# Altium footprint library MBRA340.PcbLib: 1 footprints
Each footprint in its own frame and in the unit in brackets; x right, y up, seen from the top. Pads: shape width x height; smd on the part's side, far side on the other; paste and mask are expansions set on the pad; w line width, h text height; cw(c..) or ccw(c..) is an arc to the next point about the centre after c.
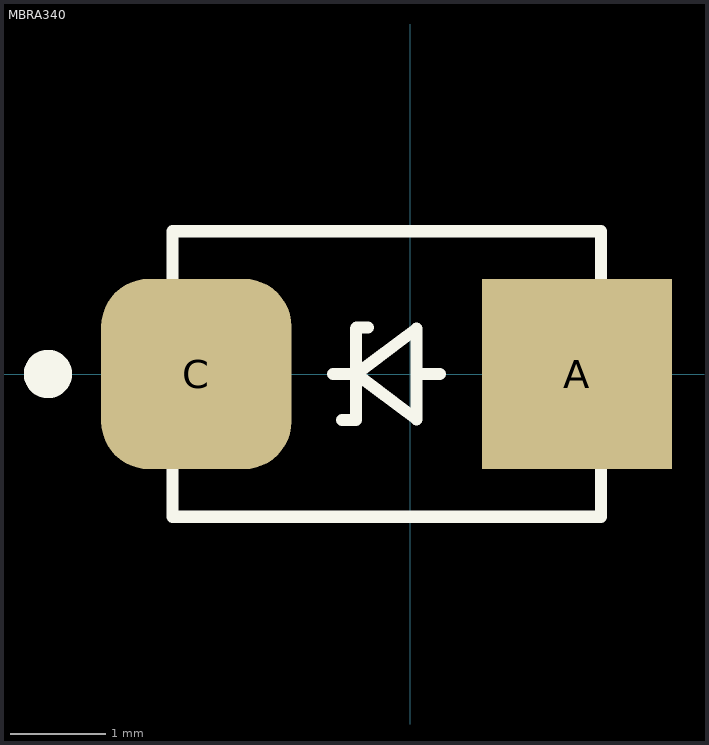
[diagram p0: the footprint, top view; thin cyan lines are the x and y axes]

## MBRA340 [mm]
pads (2):
  rect 2x2 smd: A(1.75,0)
  rrect50% 2x2 smd: C(-2.25,0)
Top Overlay:
  circle w0.254: c-3.81,0 r0.127
  lines w0.127: -0.815,0 -0.572,0 ; -0.721,-0.482 -0.574,-0.482 ; -0.572,-0.478 -0.572,0 ; -0.572,0.476 -0.572,0 ; -0.566,0.49 -0.445,0.49 ; 0.307,0 0.064,0 ; -0.572,0 0.064,-0.476 0.064,0 ; -0.572,0 0.064,0.476 0.064,0 ; -2.5,-1.5 2,-1.5 2,1.5 -2.5,1.5 -2.5,-1.5
3D body "MBRA340.STEP": height 2.14, standoff -0.06, extent -2.859,-1.3 2.351,1.3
